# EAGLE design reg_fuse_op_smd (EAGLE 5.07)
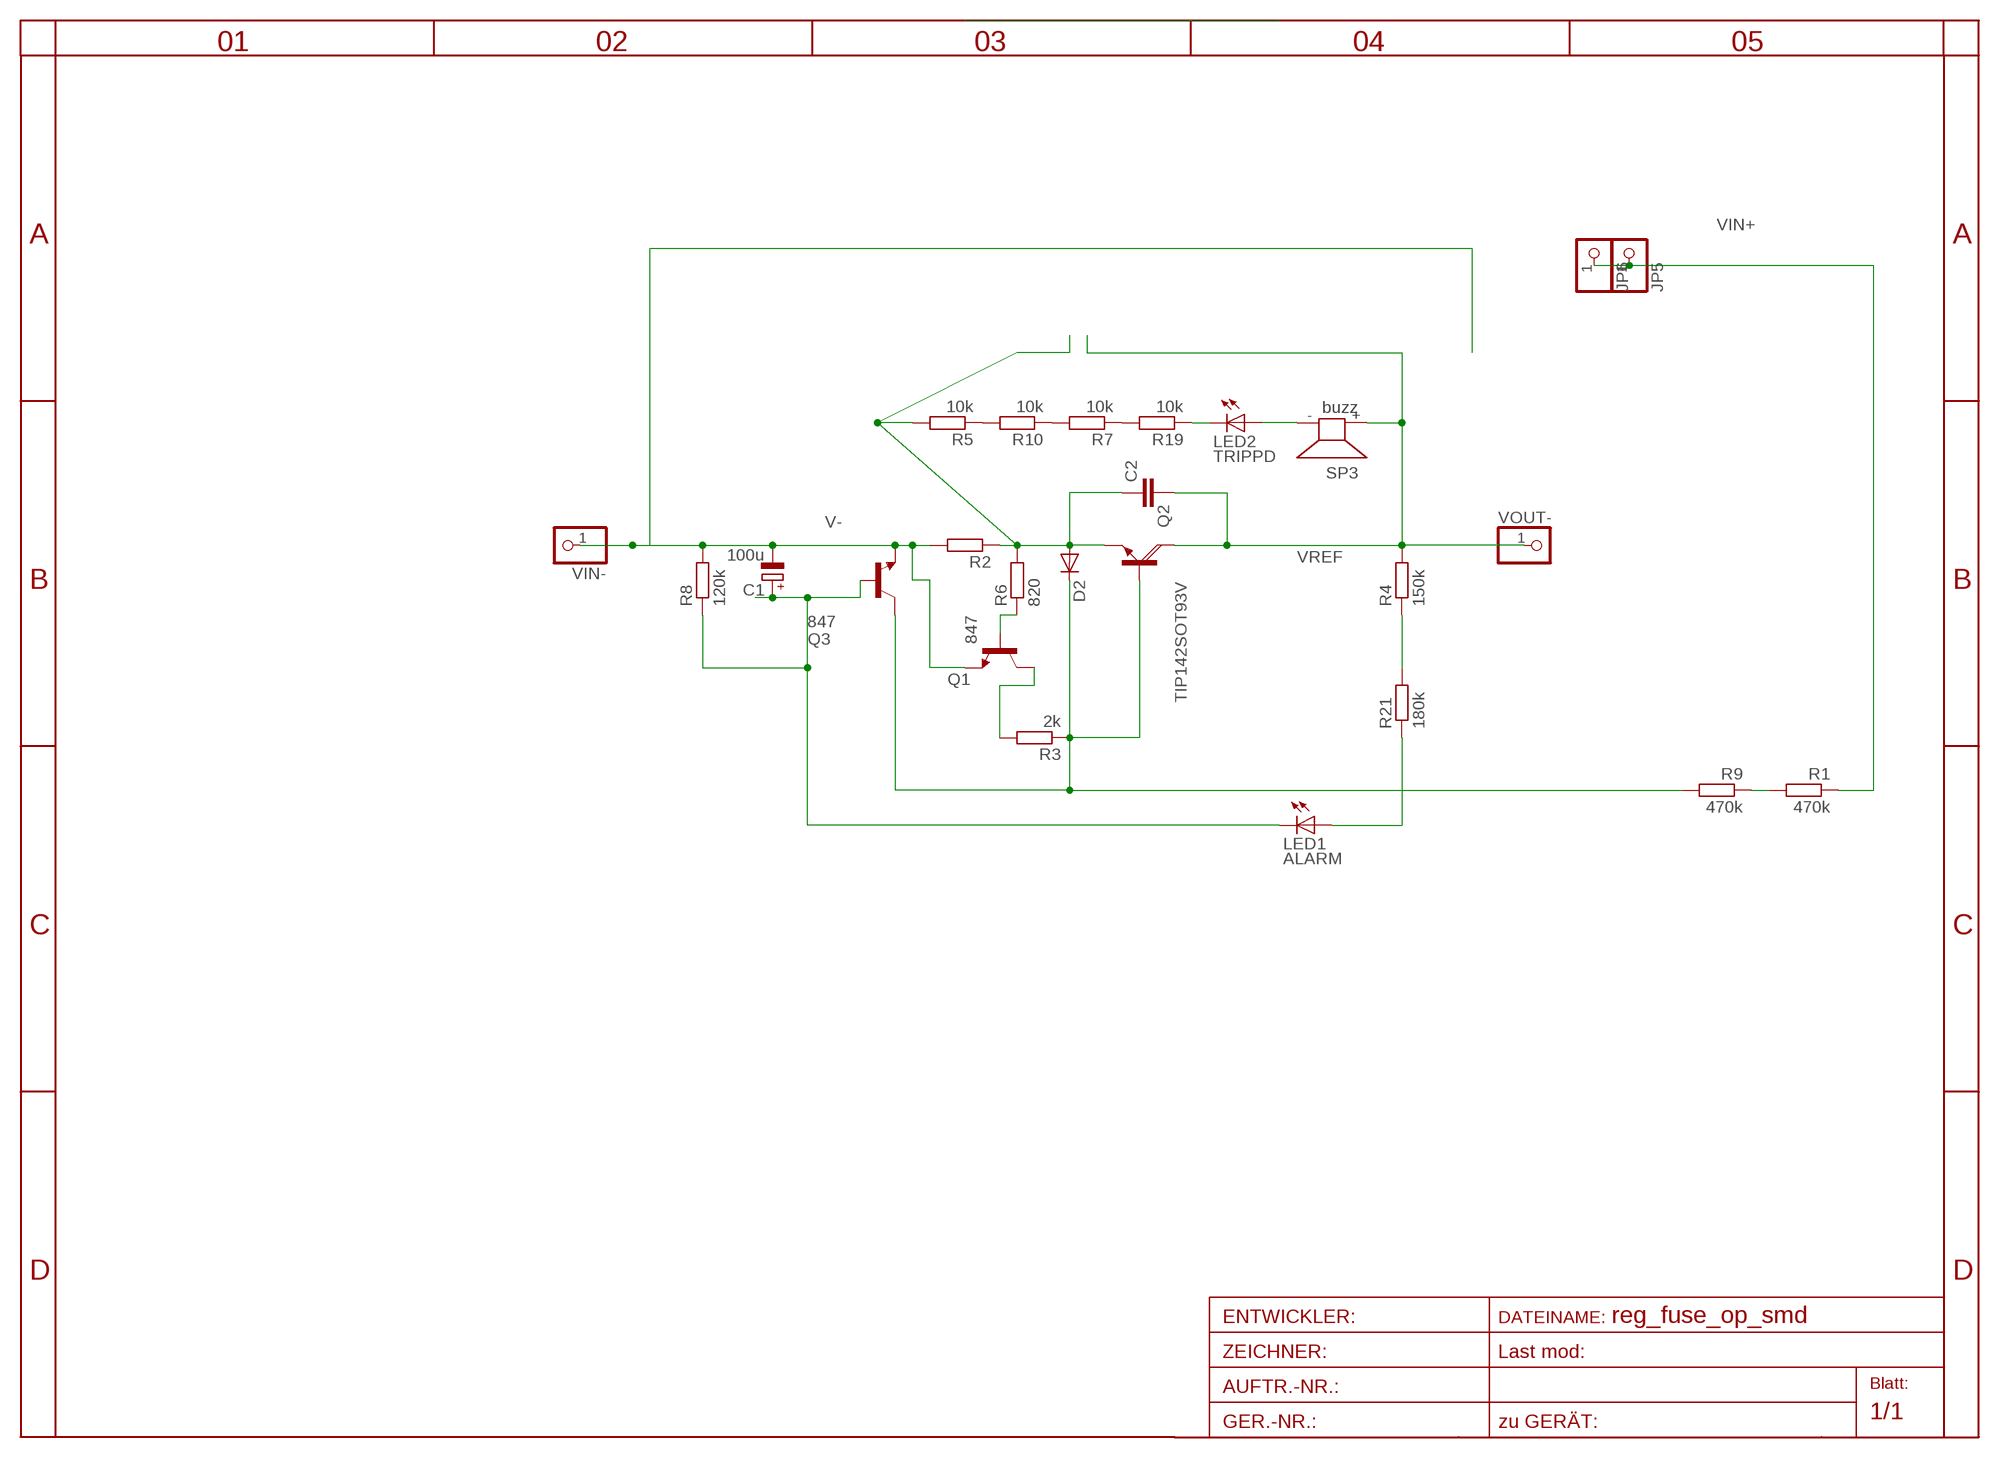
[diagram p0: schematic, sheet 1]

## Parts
C1  100u  CPOL-EUE2.5-5  [E2,5-5]
C2  C-EU225-062X268  [C225-062X268]
D2  DIODE-MINIMELF  [MINIMELF]
JP5  PINHD-1X12MM3  [1X2MM3]
JP6  PINHD-1X12MM3  [1X2MM3]
LED1  ALARM  LED5MM  [LED5MM]
LED2  TRIPPD  LED5MM  [LED5MM]
Q1  847  BC847ALT1SMD  [SOT23]
Q2  TIP142SOT93V  [SOT93V]
Q3  847  BC847ALT1SMD  [SOT23]
R1  470k  R-EU_R1206  [R1206]
R2  R-EU_0411/12  [0411/12]
R3  2k  R-EU_R0805  [R0805]
R4  150k  R-EU_R1206  [R1206]
R5  10k  R-EU_R1206  [R1206]
R6  820  R-EU_R1206  [R1206]
R7  10k  R-EU_R1206  [R1206]
R8  120k  R-EU_R0805  [R0805]
R9  470k  R-EU_R1206  [R1206]
R10  10k  R-EU_R1206  [R1206]
R19  10k  R-EU_R1206  [R1206]
R21  180k  R-EU_R1206  [R1206]
SP3  buzz  KSS12017MM  [KSS1202]
VIN-  PINHD-1X12MM3  [1X2MM3]
VOUT-  PINHD-1X12MM3  [1X2MM3]

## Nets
E1: C2.1 D2.A Q2.E R2.1 R5.2 R6.2
N$1: R7.2 R10.1
N$2: R5.1 R10.2
N$4: D2.C Q2.B Q3.3(C) R3.1 R9.2
N$6: Q1.1(B) R6.1
N$7: Q1.3(C) R3.2
N$9: LED2.K(C) R19.1
N$11: LED1.A R21.1
N$13: LED2.A SP3.-
N$20: R1.2 R9.1
N$21: R7.1 R19.2
N$22: R4.1 R21.2
SIGN: C1.+ LED1.K(C) Q3.1(B) R8.1
V-: C1.- Q1.2(E) Q3.2(E) R2.2 R8.2 VIN-.1
VIN+: JP5.1 JP6.1 R1.1
VREF: C2.2 Q2.C R4.2 SP3.+ VOUT-.1

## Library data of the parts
C1 = rcl:CPOL-EU: POLARIZED CAPACITOR, European symbol
C2 = rcl:C-EU: CAPACITOR, European symbol
D2 = diode-1:DIODE-: DIODE
JP5 JP6 VIN- VOUT- = pinhead:PINHD-1X1: PIN HEADER
LED1 LED2 = led:LED: LED
Q1 Q3 = transistor-npn:BC847*: NPN Transistor
Q2 = transistor-power:TIP142: NPN DARLINGTON TRANSISTOR
R1-R5 R7-R10 R19 = rcl-2:R-EU_: RESISTOR, European symbol
R6 R21 = rcl:R-EU_: RESISTOR, European symbol
SP3 = buzzer:KSS1201: SPEAKER

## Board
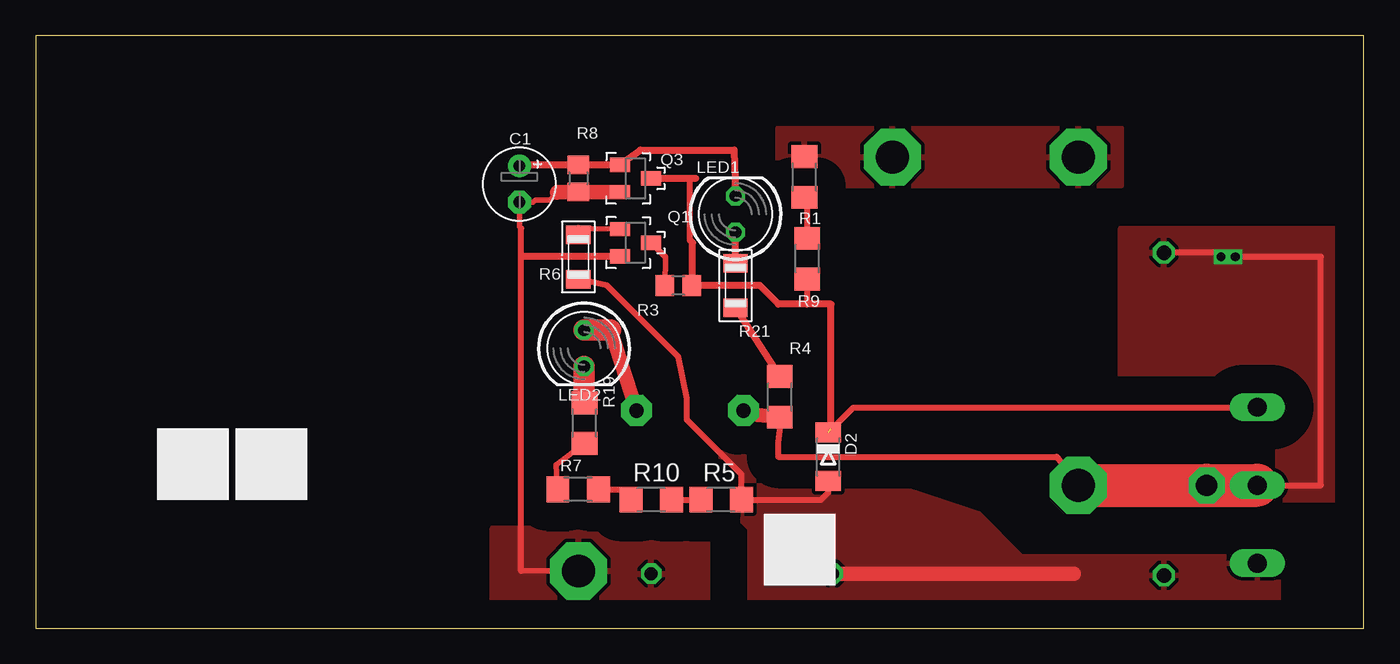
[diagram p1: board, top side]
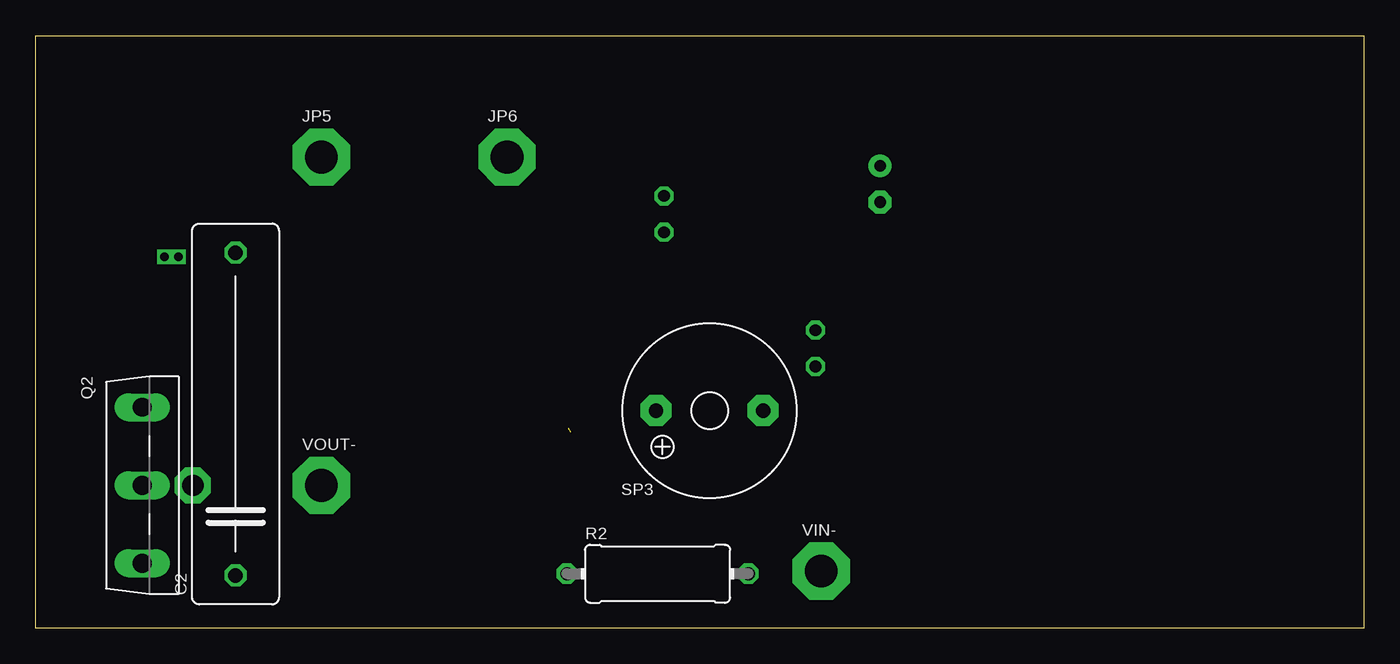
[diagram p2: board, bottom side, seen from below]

Size 93 x 41.5 mm. Coordinates in mm from the lower left corner, seen from the top.
Outline: 0,0 93,0 93,41.5 0,41.5 0,0
Copper layers (1*16): Top 0.035mm / dielectric 1.5mm / Bottom 0.035mm
Design rules "default *": minimum track width 10mil, minimum drill 2mil, track to track 8mil, track to pad 8mil, pad to pad 8mil, via to via 8mil, smd to smd 8mil, copper to edge 40mil, drill to drill 8mil, minimum pad ring 10mil, minimum via ring 8mil, stop-mask expansion 4mil, vias tented up to drill 0mil, thermal gap 10mil

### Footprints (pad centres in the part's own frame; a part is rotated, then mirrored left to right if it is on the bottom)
E2,5-5 = drill 0.813 pad 1.6 round: + -1.27,0 | drill 0.813 pad 1.6 octagon: - 1.27,0
C225-062X268 = drill 1.016 octagon: 1 -11.303,0; 2 11.303,0
MINIMELF = smd 1.4 x 1.8: A 1.7,0; C -1.7,0
1X2MM3 = drill 2.3 pad 4 octagon: 1 0,0
LED5MM = drill 0.813 octagon: A -1.27,0; K 1.27,0
SOT23 = smd 1 x 1.4: 1 -0.95,-1.1; 2 0.95,-1.1; 3 0,1.1
SOT93V = drill 1.3 pad 1.676 long: B -5.461,-2.54; C 0,-2.54; E 5.461,-2.54
R1206 = smd 1.6 x 1.803: 1 -1.422,0; 2 1.422,0
0411/12 = drill 0.914 octagon: 1 -6.35,0; 2 6.35,0
R0805 = smd 1.3 x 1.5: 1 -0.95,0; 2 0.95,0
R1206' = smd 1.3 x 1.7: 1 -1.55,0; 2 1.55,0
KSS1202 = drill 1 pad 2.159 octagon: + 3.75,0; - -3.75,0

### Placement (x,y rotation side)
C1  33.87,31.11 270 top
C2  79,15 90 bottom
D2  55.5,12 270 top
JP5  73,33 0 bottom
JP6  60,33 0 bottom
LED1  49,29 90 top
LED2  38.4,19.6 270 top
Q1  42,27 270 top
Q2  83,10 270 bottom
Q3  42,31.5 270 top
R1  53.83,31.59 270 top
R2  49.45,3.81 0 bottom
R3  45,24 180 top
R4  52.1,16.2 270 top
R5  48,9 0 top
R6  820  [R1206']  38,26 270 top
R7  37.98,9.71 0 top
R8  38,31.5 270 top
R9  54.03,25.88 270 top
R10  43.1,9 0 top
R19  38.43,14.36 270 top
R21  180k  [R1206']  49,24 270 top
SP3  45.81,15.24 180 bottom
VIN-  38,4 0 bottom
VOUT-  73,10 0 bottom

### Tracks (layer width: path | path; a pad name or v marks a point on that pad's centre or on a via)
E1
  Top 0.406: R6.2 40,24 45,19 45.6,16.1 45.6,14.6 49.42,10.78 R5.2 55,9 55.5,9.5 D2.A
  Top 1: R2.1 72.7,3.81
  pour Top (isolate 2, rank 2): 48,14 48,8 49,8 50,7 50,1 87,2 87,5 69,5 66,8
N$1
  Top 0.406: R7.2 40.97,9.71 R10.1
N$2
  Top 0.406: R10.2 R5.1
N$4  (1 unrouted)
  Top 0.406: 46.21,31.5 45.83,31.5 45.83,27.18 | R9.2 54.03,22.73 54,22.7 | 85.05,15.45 57.24,15.45 D2.C
  Top 0.5: 55.7,14 55.7,22.7 54,22.7 52,22.7 50.7,24 R3.1 46,24.05 46,27 45.83,27.18 | 46.21,31.5 Q3.3
  Top 1: 85.05,15.45 Q2.B
N$6
  Top 0.4: 38,28 38.9,28 Q1.1
  Top 0.5: R6.1 38,28
N$7
  Top 0.4: R3.2 44.1,26 Q1.3
N$9
  Top 0.4: R19.1 38.4,16.01
  Top 1.5: 38.4,16.01 LED2.K
N$11
  Top 0.5: R21.1 LED1.A
N$13
  Top 1: SP3.- 40.23,20.87
  Top 1.5: 40.23,20.87 LED2.A
N$20
  Top 0.406: R9.1 54.03,29.97 R1.2
N$21
  Top 0.4: R19.2 36.43,11.44 R7.1
N$22
  Top 0.5: R4.1 R21.2
SIGN
  Top 0.5: LED1.K 48.9,33.5 42.35,33.5 Q3.1 R8.1 33.94,32.45 C1.+
V-
  Top 0.4: 34,4 VIN-.1 | 34,28 33.87,28.13 C1.- 34.84,29.84 35,30 36,30 36.5,30.5
  Top 0.406: 34.05,26.05 34,26.05 | 34,4 34,26 34,26.05 | 34,26.05 34,28
  Top 0.5: Q1.2 34.05,26.05 34,26
  Top 1: Q3.2 R8.2 36.55,30.55 36.5,30.5
  pour Top (isolate 2): 32,7 47,7 47,1 32,1 32,3
VIN+
  pour Top (isolate 2): 52,35 76,35 76,31 52,31
VREF  (via drill 0.6, 1.5 pad 2.54)
  Top 0.406: C2.2 83,26.3 v83,26 | v84,26 90,26 90,10 Q2.C | R4.2 52.1,13.9 52,13 52,12 71.5,12 VOUT-.1
  Top 1: R4.2 50.1,14.98 SP3.+
  Top 3: Q2.C v82,10 VOUT-.1
  Bottom 0.406: v84,26 v83,26
  pour Top (isolate 2): 76,28 92,28 92,9 87,9 87,13 88,13 88,17 76,17 76,18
